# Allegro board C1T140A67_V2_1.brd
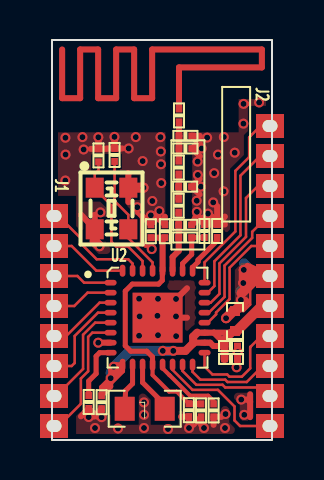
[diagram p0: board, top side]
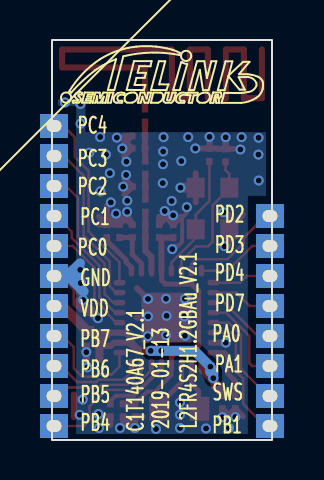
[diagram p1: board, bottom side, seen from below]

Outline 11 x 20 mm; copper layers: TOP, BOTTOM. Coordinates in mm from the lower left corner of the outline.
Outline path: rectangle 0,0 11,20 ; 0,20 11,20 11,0 0,0 0,20

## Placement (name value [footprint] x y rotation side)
C2  NC  [0201]  3.13 14.25 270 top
C3  NC  [0201]  2.32 14.23 270 top
C4  0.1uF  [0201]  4.94 10.44 270 top
C5  2.2uF  [0201]  5.64 10.44 270 top
C6  1.5pF  [0201]  6.66 10.76 0 top
C7  1.5pF  [0201]  6.66 12.67 0 top
C8  2pF  [0201]  6.67 14.58 0 top
C10  220pF  [0201]  6.33 11.71 90 top
C12  2.4nH  [0201]  6.67 15.21 0 top
C13  18pF  [0201]  7.62 10.45 90 top
C14  1uF  [0201]  8.26 10.45 90 top
C15  1uF  [0201]  1.84 1.9 90 top
C16  1uF  [0201]  8.95 4.7 0 top
C17  0.1uF  [0201]  8.95 4.05 0 top
C18  10uF  [0402]  9.15 5.95 90 top
C19  1uF  [0201]  2.48 1.89 270 top
C20  0.1uF  [0201]  6.84 1.49 270 top
C21  1uF  [0201]  7.45 1.48 270 top
C22  1uF  [0201]  8.08 1.48 270 top
J1  HEADER 8  [HDR_1P5_1X8]  0 11.2 270 top
J2  HEADER 11  [HDR_1P5_1X11]  11 15.7 90 top
L3  2.2nH  [0201]  6.34 13.62 90 top
L4  1nH  [0201]  6.35 16.23 90 top
L5  1.3nH  [0201]  6.66 10.13 180 top
L6  47uH  [0805L]  4.64 1.56 180 top
U2  TLSR8258F512ET32  [QFN_5X5_32PIN_0P5_2P50X2P50]  5.28 6.12 0 top
Y1  24MHz-12pF-+/-20ppm  [OSCCC200X250X080]  2.98 11.58 0 top

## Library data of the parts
C2 C3 = C1005_NC: User Part Number: pn; Tolerance: RichardLC
C4 C5 C16 C17 C19-C22 = C1005X5R1C104K: User Part Number: pn; Tolerance: RichardLC
C6-C8 C12 = C1005C0G1H020C: User Part Number: pn; Tolerance: RichardLC
C10 = C1608_NC: User Part Number: pn; Tolerance: RichardLC
C13 = C1005C0G1H100D: User Part Number: pn; Tolerance: RichardLC
C14 = C1608X5R1C105M: User Part Number: pn; Tolerance: RichardLC
C15 = C1005X5R1C105K: User Part Number: pn; Tolerance: RichardLC
C18 = C1608X5R0J106M
J1 = HEADER 8
J2 = HEADER 11
L3 L4 = MLK1005S3N3ST: User Part Number: pn; Tolerance: RichardLC
L5 = MLK1608_000R: User Part Number: pn; Tolerance: RichardLC
L6 = IND_0
U2 = TLSR8258F512ET32
Y1 = CRYSTAL4/SM_0

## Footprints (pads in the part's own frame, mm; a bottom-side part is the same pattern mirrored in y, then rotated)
0201
  rect 0.35x0.33 smd: 1(-0.325,0) 2(0.325,0)
0402
  rect 0.5x0.5 smd: 1(-0.5,0) 2(0.5,0)
0805L
  rect 1x1.2 smd: 1(-1,0) 2(1,0)
HDR_1P5_1X8
  rect 1.2x1.4 hole 0.6x0.75: 1(0,0.1) 2(1.5,0.1) 3(3,0.1) 4(4.5,0.1) 5(6,0.1) 6(7.5,0.1) 7(9,0.1) 8(10.5,0.1)
HDR_1P5_1X11
  rect 1.2x1.4 hole 0.6x0.75: 1(0,0.1) 2(-1.5,0.1) 3(-3,0.1) 4(-4.5,0.1) 5(-6,0.1) 6(-7.5,0.1) 7(-9,0.1) 8(-10.5,0.1) 9(-12,0.1) 10(-13.5,0.1) 11(-15,0.1)
OSCCC200X250X080
  rect 0.9x1 smd: 1(-0.84,1.04) 2(-0.84,-1.04) 3(0.84,-1.04) 4(0.84,1.04)
QFN_5X5_32PIN_0P5_2P50X2P50
  oval 0.6x0.28 smd: 1(-2.35,1.75) 2(-2.35,1.25) 3(-2.35,0.75) 4(-2.35,0.25) 5(-2.35,-0.25) 6(-2.35,-0.75) 7(-2.35,-1.25) 8(-2.35,-1.75) 17(2.35,-1.75) 18(2.35,-1.25) 19(2.35,-0.75) 20(2.35,-0.25) 21(2.35,0.25) 22(2.35,0.75) 23(2.35,1.25) 24(2.35,1.75)
  oval 0.28x0.6 smd: 9(-1.75,-2.35) 10(-1.25,-2.35) 11(-0.75,-2.35) 12(-0.25,-2.35) 13(0.25,-2.35) 14(0.75,-2.35) 15(1.25,-2.35) 16(1.75,-2.35) 25(1.75,2.35) 26(1.25,2.35) 27(0.75,2.35) 28(0.25,2.35) 29(-0.25,2.35) 30(-0.75,2.35) 31(-1.25,2.35) 32(-1.75,2.35)
  rect 2.5x2.5 smd: 33(0,0)

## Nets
1V2: C4.2 C5.2 C20.1 C21.1 U2.12(VDD1V2) U2.28(AVDD1V2)
GND: C2.1 C3.1 C4.1 C5.1 C6.2 C7.2 C8.2 C12.2 C13.2 C14.2 C15.1 C16.2 C17.2 C18.2 C19.2 C20.2 C21.2 C22.2 J2.6 U2.7(DVSS) U2.33(GND) Y1.2 Y1.4
TL_ANT: C6.1 C10.1 L5.2 U2.27(ANT)
TL_B4: J2.11 U2.14(SDMP0/P4/B[4])
TL_B5: J2.10 U2.15(SDMN0/P5/B[5])
TL_B6: J2.9 U2.16(SDMP1/DI/URTS/B[6])
TL_C0: J2.5 U2.20(I2C_SDA/P4N/URTS/C[0])
TL_C1: J2.4 U2.21(I2C_SCK/P1N/P0/C[1])
TL_C2: J2.3 U2.22(P0/7816_TRX/I2C_SDA/32KOUT/C[2])
TL_C3: J2.2 U2.23(P1/URX/I2C_SCK/32KIN/C[3])
TL_C4: J2.1 U2.24(P2/UCTS/P0N/BIAS/C[4])
TL_GPIO0: J1.3 U2.1(SWM/I2S_SDO/P2N/D[4])
TL_GPIO1: J1.2 U2.32(P1N/I2S_SDI/7816_TRX/D[3])
TL_GPIO2: J1.1 U2.31(CN/I2S_LR/P3/D[2])
TL_GRANT: J1.4 U2.2(CK/I2S_BCK/7816_TRX/D[7])
TL_PRIORITY: J1.5 U2.3(DMIC_DI/P0N/URX/A[0])
TL_REQUEST: J1.6 U2.4(DMIC_CLK/7816_CLK/I2S_CLK/A[1])
TL_SWS: J1.7 U2.5(SWS/URTS/A[7])
TL_URX: J2.8 U2.17(SDMN1/DO/URX/B[7])
TL_UTX: J1.8 U2.6(P4/UTX/ATSEL2/B[1])
TL_VDD: C16.1 C17.1 C18.1 C19.1 J2.7 U2.9(VDD_IO) U2.18(VDD3) U2.19(VDDIO_AMS)
TL_XC1: C2.2 U2.29(XC1) Y1.3
TL_XC2: C3.2 U2.30(XC2) Y1.1
N19775240: C13.1 L5.1 U2.26(VANT)
N19775250: C14.1 U2.25(RESETB)
N19775943: C7.1 C10.2 L3.1
N19776303: C15.2 U2.8(VDD1V)
N19776990: L6.1 U2.11(VDCDC)
N19777000: L6.2 U2.10(VDCDC_SW)
N19777002: C22.1 U2.13(VDD_F)
N19779349: C8.1 C12.1 L3.2 L4.1
N19782384: L4.2

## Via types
v1: diameter 0.5, hole 0.3, TOP to BOTTOM, 73 vias

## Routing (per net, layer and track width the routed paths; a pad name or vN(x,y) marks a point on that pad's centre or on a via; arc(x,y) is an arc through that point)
1V2: length 13.2
  TOP w0.2: C20.1 6.24,2.42 5.86,2.42 5.03,3.25 U2.12
  TOP w0.25: U2.28 5.52,8.45 5.52,7.98 5.33,7.79 4.01,7.79 3.66,7.44 3.66,4.71 3.94,4.44 4.74,4.44 5.03,4.15 U2.12
  TOP w0.3: C20.1 6.85,1.81 C21.1 ; U2.28 5.53,10 C5.2 C4.2
GND: length 52.3
  TOP w0.127: 9.78,8.71 9.91,8.58 9.91,6.77 9.58,6.45 C18.2
  TOP w0.2: v1(4.99,9.54) 4.82,9.71 4.68,9.71 4.49,9.9 4.49,11.13 4.26,11.36 v1(4.26,11.64)
  TOP w0.3: C2.1 3.13,14.97 ; C2.1 3.52,14.58 ; C2.1 2.74,14.58 ; C2.1 3.12,14.58 v1(3.12,15.16) ; 9.39,6.92 C18.2 9.62,6.69 ; C7.2 7.38,12.28 ; C7.2 v1(7.44,12.67) ; C7.2 7.38,13.05 ; U2.7 v1(2.31,4.87) ; 2.29,1.17 C19.2 ; C19.2 v1(2.48,1.14) ; C19.2 2.09,1.17 ; C13.2 8.01,11.17 ; C13.2 C14.2 ; C13.2 7.62,11.14 v1(7.8,11.32) 7.8,11.32 8.26,10.86 ; C13.2 7.23,11.17 ; v1(9.23,3.63) 9.28,3.68 C17.2 9.28,4.38 v1(9.29,4.39) 9.28,4.4 9.28,4.7 ; C14.2 8.64,11.17 ; C14.2 8.64,10.77 ; C14.2 8.26,10.86 ; 9.78,7.69 J2.6 9.78,8.71 ; 6.84,0.77 C20.2 6.46,1.16 ; v1(9.46,2.02) 9.79,2.02 9.91,1.91 ; C8.2 v1(7.48,14.58) ; C8.2 7.39,14.96 ; C8.2 7.39,14.19 ; 6.75,6.12 U2.33 6.75,7.59 ; 3.82,13.34 Y1.4 3.82,11.89 ; C15.1 v1(1.84,1.15) ; C15.1 1.45,1.18 ; C15.1 2.22,1.18 ; v1(2.32,15.14) 2.32,14.56 C3.1 ; 1.46,11.26 Y1.2 2.14,11.26 ; v1(7.24,11.41) 7.24,11.02 C6.2 ; 4.55,11.16 C4.1 ; C4.1 v1(4.94,11.23) ; C4.1 5.33,11.16 ; 9.91,1.91 9.91,1.14 ; 9.91,1.91 9.91,2.29 ; 8.26,10.86 8.26,11.68 v1(8.06,11.88) ; C3.1 2.32,14.95 ; C3.1 1.94,14.56 ; C3.1 2.71,14.56 ; 7.07,0.76 C21.2 7.45,0.76 ; 7.39,14.82 C12.2 7.39,15.21 ; 8.47,1.16 C22.2 8.08,0.76 ; C6.2 7.38,11.15 ; C6.2 7.18,11.15 ; v1(9.58,16.81) 9.72,16.81 ; 5.25,11.16 C5.1 5.64,11.16
  TOP w0.5: v1(8.7,6.09) 9.06,6.45 C18.2 9.62,6.92 ; J2.6 10.34,8.2 ; 10.34,8.2 9.91,8.2 ; 10.34,8.2 9.48,7.34 ; 9.59,7.87 9.91,8.2 ; 9.59,7.87 v1(9.56,7.85) ; 9.59,7.87 v1(9.59,8.51) 9.9,8.2 9.91,8.2 ; Y1.2 2.14,9.92 v1(2.37,9.69) ; Y1.4 v1(4.58,12.62)
  BOTTOM w0.5: v1(9.59,8.51) 9.9,8.2 9.91,8.2 ; 9.91,8.2 v1(9.56,7.85) ; 9.91,8.2 10.19,8.2 ; 10.23,8.2 9.6,8.83 ; 10.23,8.2 J2.6 ; 10.23,8.2 10.19,8.2 ; 10.19,8.2 9.42,7.43
  vias: v1(0.67,15.11) v1(0.68,14.27) v1(0.67,12.97) v1(1.52,15.14) v1(1.58,14.53) v1(2.15,0.6) v1(2.42,11.38) v1(3.3,0.58) v1(3.83,14.58) v1(4.19,15.14) v1(4.36,7.06) v1(4.38,6.18) v1(4.35,5.21) v1(4.53,13.95) v1(4.6,1.88) v1(4.6,1.26) v1(4.6,0.6) v1(5.02,11.95) v1(5.3,7.06) v1(5.27,6.21) v1(5.3,5.24) v1(5.42,15.14) v1(5.44,14.43) v1(5.45,13.79) v1(5.37,11.45) v1(5.46,12.85) v1(5.8,0.55) v1(6.2,7.05) v1(6.2,6.18) v1(6.21,5.19) v1(6.85,0.6) v1(7.24,11.96) v1(7.28,13.92) v1(7.29,13.25) v1(7.6,0.6) v1(7.76,15.12) v1(8.11,13.34) v1(8.3,14.27) v1(8.59,15.15) v1(8.58,12.43) v1(8.68,1.3) v1(8.65,0.6) v1(9.14,14.37) v1(9.44,7) v1(9.57,15.82) v1(9.61,1.26) v1(10.36,16.88)
TL_ANT: length 3
  TOP w0.3: C10.1 C6.1 L5.2 6.33,9.45 6.03,9.15 U2.27
TL_B4: length 6.7
  TOP w0.127: U2.14 6.03,3.5 7.02,2.51 8.29,2.51 9.13,1.68 9.13,0.98 9.4,0.7 J2.11
TL_B5: length 5.2
  TOP w0.127: U2.15 6.53,3.45 7.22,2.76 8.53,2.76 8.66,2.63 10.47,2.63 J2.10
TL_B6: length 4.8
  TOP w0.127: U2.16 7.03,3.41 7.42,3.02 8.66,3.02 8.78,2.9 9.74,2.9 10.54,3.7 J2.9
TL_C0: length 5.8
  TOP w0.127: J2.5 9.96,9.7 8.88,8.62 8.88,7.06 8.88,7.05 8.87,7.04 8.2,6.37 8.2,6.28 7.79,5.87 U2.20
TL_C1: length 6.4
  TOP w0.127: U2.21 7.84,6.37 8.63,7.15 8.63,8.72 10.01,10.11 10.01,10.41 10.8,11.2 J2.4
TL_C2: length 7.7
  TOP w0.127: J2.3 10.3,12.7 9.7,12.1 9.7,10.15 8.37,8.83 8.37,7.31 7.93,6.87 U2.22
TL_C3: length 8.6
  TOP w0.127: J2.2 10.41,14.2 9.42,13.22 9.42,10.24 8.12,8.93 8.12,7.7 7.79,7.37 U2.23
TL_C4: length 9.5
  TOP w0.127: U2.24 7.63,8.89 9.17,10.43 9.17,13.46 9.86,14.15 9.86,15.14 10.42,15.7 J2.1
TL_GPIO0: length 3
  TOP w0.127: U2.1 1.6,7.87 1.27,8.2 J1.3
TL_GPIO1: length 3.9
  TOP w0.127: U2.32 2.22,8.47 0.98,9.7 J1.2
TL_GPIO2: length 5.4
  TOP w0.127: U2.31 4.03,8.82 3.81,9.04 2.23,9.04 1.42,9.85 1.42,10.11 0.33,11.2 J1.1
TL_GRANT: length 3.1
  TOP w0.127: U2.2 1.78,7.37 1.11,6.7 J1.4
TL_PRIORITY: length 3.5
  TOP w0.127: U2.3 2.38,6.87 0.71,5.2 J1.5
TL_REQUEST: length 4.7
  TOP w0.127: J1.6 0.98,3.7 1.13,3.85 1.13,5.2 2.3,6.37 U2.4
TL_SWS: length 5.3
  TOP w0.127: U2.5 2.16,5.87 1.55,5.26 1.55,3.55 0.2,2.2 J1.7
TL_URX: length 5.6
  TOP w0.127: J2.8 10.47,5.2 9.95,4.68 9.94,4.67 9.92,4.65 9.91,4.64 9.91,4.63 9.91,3.58 9.5,3.17 8.87,3.17 8.76,3.28 8.02,3.28 7.63,3.67 U2.17
TL_UTX: length 6.5
  TOP w0.127: J1.8 0.34,0.7 1.44,1.81 1.44,3.07 1.81,3.44 1.81,5.16 2.02,5.37 U2.6
TL_VDD: length 20.8
  TOP w0.25: v1(2.94,3.09) 2.94,2.67 C19.1 2.48,2.4 ; v1(2.94,3.09) 2.94,3.52 v1(3.08,3.67) ; v1(2.94,3.09) 2.48,2.63 2.48,2.4 ; v1(2.94,3.09) 3.08,3.24 ; v1(3.08,3.67) 3.08,3.24 ; v1(3.08,3.67) 3.18,3.77 U2.9 3.53,3.68 ; 3.08,3.24 3.53,3.68 ; 3.53,3.68 3.53,3.45 2.48,2.4
  TOP w0.3: 8.1,5.37 U2.19 7.26,5.37 ; 8.1,5.37 8.86,5.37 8.92,5.3 ; 8.1,5.37 8.62,4.84 C16.1 8.07,4.7 7.91,4.87 U2.18 7.08,4.87 7.06,4.84
  TOP w0.4: 7.26,5.37 7.06,5.17 7.06,4.84 6.67,4.46 v1(6.06,4.46) v1(5.54,4.46) ; C16.1 8.63,4.7 C17.1 ; 8.62,4.84 8.63,4.84 8.63,5.01 9.07,5.45 C18.1
  TOP w0.5: C18.1 9.24,5.45 10.49,6.7 J2.7
  BOTTOM w0.5: 3.04,3.41 3.08,3.41 v1(3.08,3.67) 3.87,4.46 v1(5.54,4.46) v1(6.06,4.46) ; 3.04,3.41 2.99,3.41 ; 3.04,3.41 3.04,3.45 2.99,3.45 2.99,3.41 ; 2.99,3.41 2.99,3.38 2.94,3.38 v1(2.94,3.09)
TL_XC1: length 6.2
  TOP w0.127: C2.2 3.13,11.95 3.82,11.26 Y1.3 3.82,10.09 5.03,8.88 U2.29
TL_XC2: length 6.9
  TOP w0.127: U2.30 4.53,8.95 3.8,9.68 3.2,9.68 2.97,9.91 2.97,11.73 2.14,12.57 Y1.1 2.14,13.3 2.32,13.49 C3.2
N19775240: length 2.5
  TOP w0.25: U2.26 6.53,8.82 6.98,9.28 L5.1 7.62,10.13 C13.1
N19775250: length 2.2
  TOP w0.25: C14.1 8.26,9.96 7.3,9.01 7.3,8.9 7.03,8.63 U2.25
N19775943: length 1.3
  TOP w0.3: C10.2 C7.1 6.34,12.67 L3.1
N19776303: length 2.9
  TOP w0.25: U2.8 2.38,4.37 2.21,4.19 2.21,3.32 1.84,2.95 C15.2
N19776990: length 2.7
  TOP w0.25: U2.11 4.53,2.88 5.68,1.72 L6.1
N19777000: length 2.3
  TOP w0.25: U2.10 4.03,2.82 3.68,2.47 L6.2
N19777002: length 3.6
  TOP w0.2: C22.1 8.08,1.95 7.81,2.22 6.9,2.22 5.88,3.24 5.88,3.24 5.53,3.59 U2.13
N19779349: length 2
  TOP w0.3: L4.1 6.35,15.9 6.35,15.19 ; L3.2 6.35,13.95 C8.1 6.35,14.58 6.35,15.19 ; C12.1 6.36,15.22 6.36,15.19 6.35,15.19
N19782384: length 31.7
  TOP w0.3: L4.2 6.35,18.63 10.49,18.63 10.49,19.53 5.01,19.53 5.01,17.09 4.11,17.09 4.11,19.53 3.21,19.53 3.21,17.09 2.31,17.09 2.31,19.53 1.41,19.53 1.41,17.09 0.51,17.09 0.51,19.53

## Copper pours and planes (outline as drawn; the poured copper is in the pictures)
GND on TOP: 0.3,0.3 0.3,15.38 5.67,15.38 5.67,7.99 7.01,7.99 7.01,15.38 9.33,15.38 9.33,17.05 10.7,17.05 10.7,0.3
GND on BOTTOM: 0.3,0.3 0.3,15.38 6.15,15.38 6.15,15.38 9.33,15.38 9.33,17.05 10.7,17.05 10.7,0.3

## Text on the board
Ref Des/Silkscreen Bottom: PD2 | PD3 | PD4 | PD7 | PA1 | SWS | PA0 | PB1 | PB6 | PB5 | PB4 | PC1 | GND | VDD | PB7 | PC4 | PC3 | PC2 | PC0 | L2FR4S2H1.2GBAu_V2.1 | 2019-01-13 | C1T140A67_V2.1
COMPVAL_TYPE_TOP: C1T140A67_V2.0 | 2018-11-28
User.7: FIGURE | SIZE | 0.3 | 0.75x0.6 | DRILL CHART: TOP to BOTTOM | ALL UNITS ARE IN MILLIMETERS | PLATED | QTY | 73 | 19
